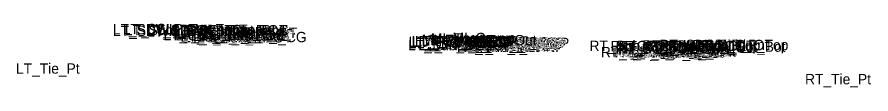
# Model space of a CAD drawing. Extents: x -26 to 4229, y -10 to 9523.
# Drawn here: x 1064.7 to 1230.2, y 5005.6 to 5017.9 of the extents above; entities that cross this region are included whole.
import ezdxf

# ---------------------------------------------------------------- set-up
doc = ezdxf.new("R2010")
doc.units = 0
doc.layers.add('Default', color=7, linetype='Continuous')

msp = doc.modelspace()

# ---------------------------------------------------------------- texts
at = {"layer": 'Default'}
for s, p in [('LT_SDWK_Out_Top', (1083.24, 5015.87)), ('LT_SDWK_Out_Bot', (1083.27, 5015.54)), ('LT_CSLP_Pnt', (1085.17, 5015.9)), ('LT_Sub_Trench_Out_DLT', (1085.58, 5015.7)), ('LT_SDWK_In_Top', (1089.86, 5015.77)), ('LT_SDWK_In_Bot', (1089.89, 5015.44)), ('LT_CG_Top_Face', (1094.76, 5015.66)), ('LT_CG_Top_BOC', (1095.28, 5015.66)), ('LT_CG1_Shelf_Out', (1093.05, 5014.69)), ('LT_CG_Bot_BOC', (1095.31, 5014.68)), ('LT_CG_Top_Gut', (1095.74, 5015.16)), ('LT_Sub_OEOP', (1096.37, 5014.45)), ('LT_Sub_OEOT_CG', (1096.87, 5014.34)), ('LT_CG_Bot_IE', (1099.41, 5014.59)), ('LT_Sub_OEOT', (1099.58, 5014.29)), ('LT_PV2_OEOT', (1099.67, 5014.92)), ('LT_PV3_OEOT', (1099.67, 5014.67)), ('LT_PV1_OEOT', (1100.24, 5015.17)), ('LT_PV1_PGL', (1143.03, 5013.67)), ('MI_Face In', (1143.15, 5013.83)), ('MI_Top In', (1144.86, 5014.08)), ('MI_Crown', (1149.07, 5014.16)), ('MI_Top Out', (1151.22, 5013.74)), ('LT_Sub_OEEOP', (1140.46, 5012.79)), ('LT_PV2_OEEOP', (1140.56, 5013.42)), ('LT_PV3_OEEOP', (1140.56, 5013.17)), ('LT_PV1_OEEOP', (1141.12, 5013.54)), ('LT_PV2_IEEOP', (1141.2, 5013.42)), ('LT_PV1_IEEOP', (1141.77, 5013.54)), ('LT_PV2_PGL1', (1142.13, 5013.42)), ('LT_PV3_PGL1', (1142.13, 5013.17)), ('LT_PV2_PGL', (1142.46, 5013.42)), ('LT_PV4_PGL', (1142.46, 5012.79)), ('MI_Bot In', (1144.13, 5013.67)), ('RT_Sub_OEEOP', (1149.92, 5012.45)), ('RT_PV2_OEEOP', (1150.01, 5013.07)), ('RT_PV3_OEEOP', (1150.01, 5012.82)), ('RT_PV1_OEEOP', (1150.58, 5013.2)), ('RT_PV2_IEEOP', (1150.66, 5013.07)), ('MI_Face Out', (1151.01, 5013.49)), ('RT_PV1_IEEOP', (1151.22, 5013.2)), ('RT_PV2_PGL1', (1151.58, 5013.07)), ('RT_PV3_PGL1', (1151.58, 5012.82)), ('RT_PV2_PGL', (1151.92, 5013.07)), ('RT_PV4_PGL', (1151.92, 5012.45)), ('MI_Bot Out', (1152.01, 5013.32)), ('RT_PV1_PGL', (1152.48, 5013.32)), ('RT_Sub_Trench_Out_DLT', (1175.62, 5012.64)), ('RT_CG_Top_Face', (1179.71, 5012.6)), ('RT_CG_Top_Gut', (1180.69, 5012.1)), ('RT_PV1_OEOT', (1181.19, 5012.25)), ('RT_CG_Top_BOC', (1181.24, 5012.6)), ('RT_SDWK_In_Top', (1185.81, 5012.71)), ('RT_SDWK_In_Bot', (1185.84, 5012.38)), ('RT_SDWK_Out_Top', (1189.19, 5012.81)), ('RT_SDWK_Out_Bot', (1189.22, 5012.48)), ('RT_Shld_O', (1195.54, 5012.8)), ('CSLP_Pnt', (1197.87, 5012.84)), ('RT_Sub_OEOT_CG', (1177.82, 5011.42)), ('RT_CG1_Shelf_Out', (1180, 5011.56)), ('RT_CG_Bot_IE', (1180.37, 5011.67)), ('RT_Sub_OEOT', (1180.53, 5011.38)), ('RT_PV2_OEOT', (1180.63, 5012)), ('RT_PV3_OEOT', (1180.63, 5011.75)), ('RT_CG_Bot_BOC', (1181.27, 5011.58)), ('RT_Sub_OEOP', (1183.82, 5011.3)), ('LT_Tie_Pt', (1064.46, 5008.24)), ('RT_Tie_Pt', (1217.39, 5006.18))]:
    msp.add_text(s, height=2, dxfattribs=at).set_placement(p)

doc.saveas('drawing.dxf')
